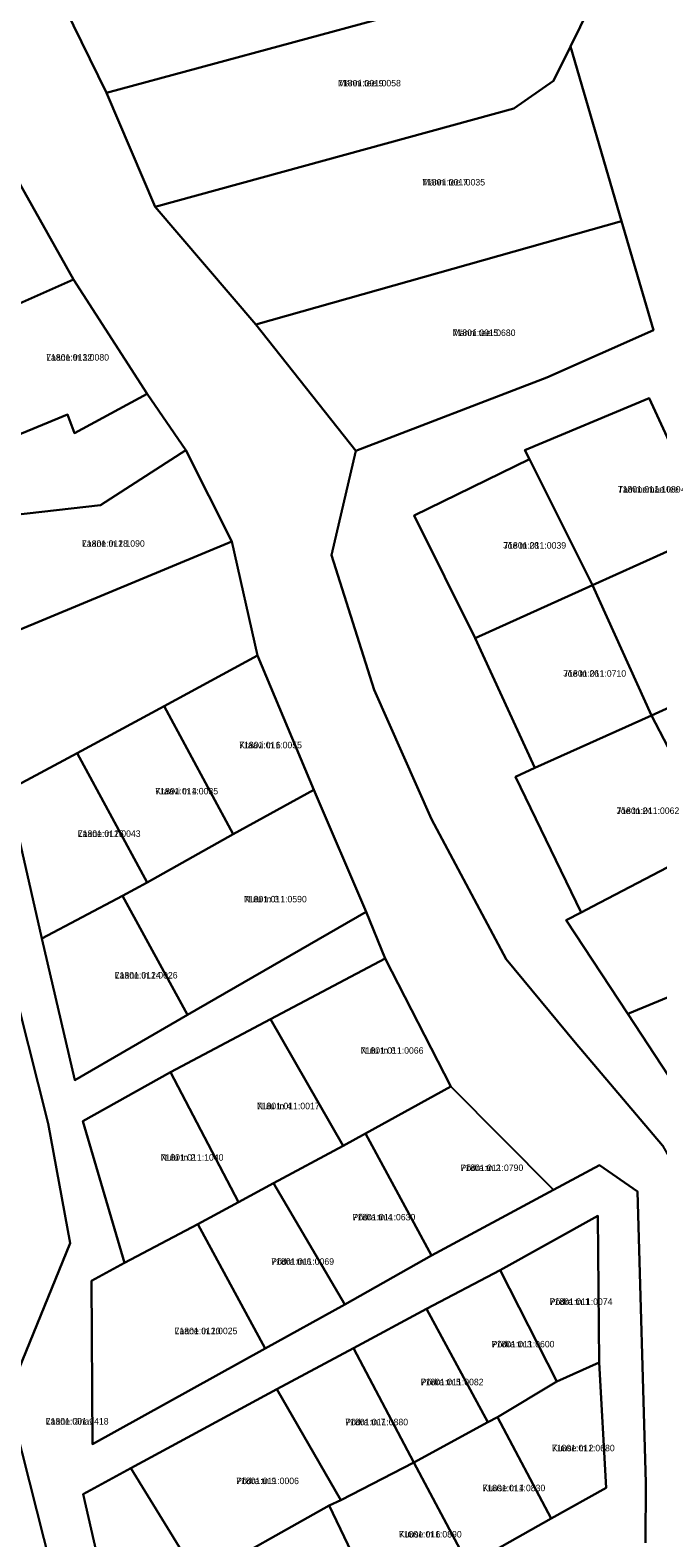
# Model space of a CAD drawing. Extents: x 529768 to 552006, y 6562269 to 6580975.
# Drawn here: x 537735.3 to 537880.2, y 6574791.4 to 6575139.4 of the extents above; entities that cross this region are included whole.
import ezdxf

# ---------------------------------------------------------------- set-up
doc = ezdxf.new("R2010")
doc.units = 0
for name, color, linetype in [('L_AADRESS', 7, 'Continuous'), ('PIIR', 7, 'Continuous'), ('TUNNUS', 7, 'Continuous')]:
    doc.layers.add(name, color=color, linetype=linetype)

msp = doc.modelspace()

# ---------------------------------------------------------------- linework, layer by layer
at = {"layer": 'PIIR'}
for points in [[(537861.04, 6575154.26), (537752.93, 6575124.92), (537739.57, 6575152.36), (537753.02, 6575156.04), (537846.64, 6575181.62)], [(537861.04, 6575154.26), (537864.51, 6575144.75), (537860.06, 6575135.67), (537856.14, 6575127.7), (537847, 6575121.36), (537764.17, 6575098.61), (537752.93, 6575124.92)], [(537847, 6575121.36), (537856.14, 6575127.7), (537860.06, 6575135.67), (537871.85, 6575095.34), (537787.43, 6575071.47), (537764.17, 6575098.61)], [(537715.01, 6575068.35), (537700.13, 6575101.13), (537691.05, 6575109.25), (537721.93, 6575123.45), (537745.3, 6575081.84), (537718.25, 6575069.88)], [(537879.22, 6575070.16), (537854.59, 6575059.21), (537810.54, 6575042.33), (537787.43, 6575071.47), (537871.85, 6575095.34)], [(537726.91, 6575046.15), (537721.22, 6575061.64), (537718.25, 6575069.88), (537745.3, 6575081.84), (537762.35, 6575055.48), (537745.6, 6575046.36), (537743.96, 6575050.67), (537728.83, 6575044.46)], [(537726.91, 6575046.15), (537728.83, 6575044.46), (537743.96, 6575050.67), (537745.6, 6575046.36), (537762.35, 6575055.48), (537771.25, 6575042.48), (537751.6, 6575029.77), (537713.53, 6575025.44), (537725.15, 6574997.87), (537716.85, 6574994.41), (537697.03, 6575023.57), (537693.76, 6575030.37), (537713.43, 6575058.2), (537721.22, 6575061.64)], [(537823.98, 6575027.38), (537838.08, 6574999.09), (537851.84, 6574969.13), (537847.37, 6574967.05), (537862.52, 6574935.76), (537859.04, 6574933.96), (537873.29, 6574912.33), (537887.42, 6574890.88), (537915.26, 6574902.32), (537943.04, 6574913.53), (537943.83, 6574915.98), (537932.32, 6574943.91), (537922.07, 6574966.37), (537915.04, 6574980.87), (537907.57, 6574994.3), (537894.96, 6575019.57), (537894.46, 6575019.54), (537892.46, 6575023.64), (537878.24, 6575054.44), (537849.52, 6575042.51), (537850.57, 6575040.41)], [(537849.52, 6575042.51), (537878.24, 6575054.44), (537892.46, 6575023.64), (537865.15, 6575011.33), (537850.57, 6575040.41)], [(537713.53, 6575025.44), (537751.6, 6575029.77), (537771.25, 6575042.48), (537781.86, 6575021.43), (537725.15, 6574997.87)], [(537850.57, 6575040.41), (537865.15, 6575011.33), (537838.08, 6574999.09), (537823.98, 6575027.38)], [(537865.15, 6575011.33), (537892.46, 6575023.64), (537894.46, 6575019.54), (537894.96, 6575019.57), (537907.57, 6574994.3), (537878.76, 6574981.24)], [(537838.08, 6574999.09), (537865.15, 6575011.33), (537878.76, 6574981.24), (537851.84, 6574969.13)], [(537782.23, 6574953.83), (537766.3, 6574983.41), (537787.82, 6574995.05), (537800.84, 6574964.08)], [(537878.76, 6574981.24), (537907.57, 6574994.3), (537915.04, 6574980.87), (537886.29, 6574966.76)], [(537746.19, 6574972.53), (537766.3, 6574983.41), (537782.23, 6574953.83), (537762.37, 6574942.71)], [(537878.76, 6574981.24), (537886.29, 6574966.76), (537892.86, 6574951.6), (537865.15, 6574937.12), (537862.52, 6574935.76), (537847.37, 6574967.05), (537851.84, 6574969.13)], [(537746.19, 6574972.53), (537762.37, 6574942.71), (537756.62, 6574939.57), (537738.05, 6574929.75), (537730.27, 6574963.99)], [(537812.88, 6574935.9), (537771.68, 6574912.1), (537756.62, 6574939.57), (537762.37, 6574942.71), (537782.23, 6574953.83), (537800.84, 6574964.08)], [(537575.1, 6574793.51), (537567.33, 6574887.8), (537721.06, 6574959.69), (537739.46, 6574887.08), (537744.59, 6574859.46), (537730.17, 6574824.12), (537691.03, 6574813.55), (537680.26, 6574772.23), (537701.22, 6574747.22), (537673.77, 6574708.6), (537642.67, 6574704.19), (537621.56, 6574706.93), (537618.19, 6574702.52), (537588.02, 6574714.43), (537548.93, 6574726.02), (537540.02, 6574788.31)], [(537859.04, 6574933.96), (537862.52, 6574935.76), (537865.15, 6574937.12), (537892.86, 6574951.6), (537902.36, 6574931.19), (537904.81, 6574925.39), (537873.29, 6574912.33)], [(537738.05, 6574929.75), (537756.62, 6574939.57), (537771.68, 6574912.1), (537745.63, 6574897.07)], [(537807.61, 6574881.89), (537790.79, 6574911.14), (537817.25, 6574925.17), (537832.47, 6574895.6), (537812.78, 6574884.74)], [(537873.29, 6574912.33), (537904.81, 6574925.39), (537915.26, 6574902.32), (537887.42, 6574890.88)], [(537790.79, 6574911.14), (537807.61, 6574881.89), (537791.48, 6574873.27), (537783.43, 6574868.9), (537767.7, 6574898.93)], [(537767.7, 6574898.93), (537783.43, 6574868.9), (537774.03, 6574863.8), (537757.12, 6574854.89), (537747.47, 6574887.56)], [(537828.01, 6574856.55), (537812.78, 6574884.74), (537832.47, 6574895.6), (537856.17, 6574871.76)], [(537807.94, 6574845.29), (537791.48, 6574873.27), (537807.61, 6574881.89), (537812.78, 6574884.74), (537828.01, 6574856.55)], [(537774.03, 6574863.8), (537783.43, 6574868.9), (537791.48, 6574873.27), (537807.94, 6574845.29), (537789.59, 6574835.11)], [(537747.59, 6574801.5), (537760.71, 6574743.92), (537787.55, 6574756.29), (537817.1, 6574772.66), (537816.46, 6574773.66), (537836.52, 6574785.11), (537855.61, 6574795.89), (537868.32, 6574802.94), (537866.69, 6574831.89), (537866.35, 6574865.77), (537843.83, 6574853.22), (537826.82, 6574844.29), (537809.98, 6574835.16), (537792.24, 6574825.71), (537758.6, 6574807.48)], [(537749.69, 6574813.04), (537749.48, 6574850.76), (537757.12, 6574854.89), (537774.03, 6574863.8), (537789.59, 6574835.11)], [(537843.83, 6574853.22), (537866.35, 6574865.77), (537866.69, 6574831.89), (537856.93, 6574827.5)], [(537856.93, 6574827.5), (537843.23, 6574819.29), (537841.02, 6574818.08), (537826.82, 6574844.29), (537843.83, 6574853.22)], [(537809.98, 6574835.16), (537826.82, 6574844.29), (537841.02, 6574818.08), (537823.9, 6574808.82)], [(537807.06, 6574800.11), (537792.24, 6574825.71), (537809.98, 6574835.16), (537823.9, 6574808.82)], [(537855.61, 6574795.89), (537843.23, 6574819.29), (537856.93, 6574827.5), (537866.69, 6574831.89), (537868.32, 6574802.94)], [(537792.24, 6574825.71), (537807.06, 6574800.11), (537804.38, 6574798.9), (537774.23, 6574781.91), (537758.6, 6574807.48)], [(537730.17, 6574824.12), (537740.19, 6574784.56), (537680.26, 6574772.23), (537691.03, 6574813.55)], [(537836.52, 6574785.11), (537823.9, 6574808.82), (537841.02, 6574818.08), (537843.23, 6574819.29), (537855.61, 6574795.89)], [(537760.71, 6574743.92), (537747.59, 6574801.5), (537758.6, 6574807.48), (537774.23, 6574781.91), (537787.55, 6574756.29)], [(537804.38, 6574798.9), (537807.06, 6574800.11), (537823.9, 6574808.82), (537836.52, 6574785.11), (537816.46, 6574773.66)], [(537804.38, 6574798.9), (537816.46, 6574773.66), (537817.1, 6574772.66), (537787.55, 6574756.29), (537774.23, 6574781.91)]]:
    msp.add_lwpolyline(points, close=True, dxfattribs=at)
for points in [[(537877.38, 6574790.27), (537877.44, 6574804.07), (537875.56, 6574871.37), (537866.76, 6574877.46), (537856.17, 6574871.76), (537832.47, 6574895.6), (537817.25, 6574925.17), (537812.88, 6574935.9), (537800.84, 6574964.08), (537787.82, 6574995.05), (537781.86, 6575021.43), (537771.25, 6575042.48), (537762.35, 6575055.48), (537745.3, 6575081.84), (537721.93, 6575123.45), (537716.1, 6575133.86), (537715.18, 6575135.41), (537718.33, 6575135.79), (537727.22, 6575136.84), (537718.28, 6575152.24)], [(537739.57, 6575152.36), (537752.93, 6575124.92), (537764.17, 6575098.61), (537787.43, 6575071.47), (537810.54, 6575042.33), (537804.89, 6575018.22), (537814.75, 6574987.16), (537827.97, 6574957.32), (537845.19, 6574925.01), (537861.18, 6574905.72), (537881.31, 6574881.94), (537891.99, 6574862.91), (537895.3, 6574837.6), (537906.26, 6574838.65), (537911.06, 6574804.7), (537903.95, 6574801.98), (537904.83, 6574769.93)], [(537881.31, 6574881.94), (537861.18, 6574905.72), (537845.19, 6574925.01), (537827.97, 6574957.32), (537814.75, 6574987.16), (537804.89, 6575018.22), (537810.54, 6575042.33), (537854.59, 6575059.21), (537879.22, 6575070.16), (537871.85, 6575095.34), (537860.06, 6575135.67), (537864.51, 6575144.75)], [(537725.15, 6574997.87), (537781.86, 6575021.43), (537787.82, 6574995.05), (537766.3, 6574983.41), (537746.19, 6574972.53), (537730.27, 6574963.99), (537738.05, 6574929.75), (537745.63, 6574897.07), (537771.68, 6574912.1), (537812.88, 6574935.9), (537817.25, 6574925.17), (537790.79, 6574911.14), (537767.7, 6574898.93), (537747.47, 6574887.56), (537757.12, 6574854.89), (537749.48, 6574850.76), (537749.69, 6574813.04), (537789.59, 6574835.11), (537807.94, 6574845.29), (537828.01, 6574856.55), (537856.17, 6574871.76), (537866.76, 6574877.46), (537875.56, 6574871.37), (537877.44, 6574804.07), (537877.38, 6574790.27)], [(537740.19, 6574784.56), (537730.17, 6574824.12), (537744.59, 6574859.46), (537739.46, 6574887.08), (537721.06, 6574959.69)]]:
    msp.add_lwpolyline(points, dxfattribs=at)

# ---------------------------------------------------------------- texts
at = {"layer": 'L_AADRESS'}
for s, p in [('Männi tee 9', (537806.41, 6575126.44)), ('Männi tee 7', (537825.84, 6575103.57)), ('Männi tee 5', (537832.88, 6575068.83)), ('Laane tn 32', (537739.03, 6575063.15)), ('Tammemäe tee 4', (537870.99, 6575032.7)), ('Laane tn 28', (537747.29, 6575020.18)), ('Jõe tn 28', (537844.56, 6575019.74)), ('Jõe tn 26', (537858.42, 6574990.19)), ('Kraavi tn 6', (537783.57, 6574973.66)), ('Kraavi tn 4', (537764.21, 6574963.01)), ('Jõe tn 24', (537870.69, 6574958.5)), ('Laane tn 26', (537746.32, 6574953.21)), ('Nulu tn 3', (537784.69, 6574938.09)), ('Laane tn 24', (537754.86, 6574920.52)), ('Nulu tn 6', (537811.63, 6574903.15)), ('Nulu tn 4', (537787.66, 6574890.34)), ('Nulu tn 2', (537765.45, 6574878.47)), ('Põdra tn 2', (537834.67, 6574876.08)), ('Põdra tn 4', (537809.74, 6574864.68)), ('Põdra tn 6', (537790.98, 6574854.44)), ('Põdra tn 1', (537855.26, 6574845.18)), ('Laane tn 20', (537768.67, 6574838.42)), ('Põdra tn 3', (537841.88, 6574835.37)), ('Põdra tn 5', (537825.5, 6574826.63)), ('Laane tänav', (537738.93, 6574817.56)), ('Põdra tn 7', (537808.07, 6574817.39)), ('Kuuse tn 2', (537855.77, 6574811.39)), ('Põdra tn 9', (537782.88, 6574803.81)), ('Kuuse tn 4', (537839.75, 6574802.17)), ('Kuuse tn 6', (537820.45, 6574791.49))]:
    msp.add_text(s, height=1.5, dxfattribs=at).set_placement(p)
at = {"layer": 'TUNNUS'}
for s, p in [('71801:001:0058', (537806.41, 6575126.44)), ('71801:001:0035', (537825.84, 6575103.57)), ('71801:001:0680', (537832.88, 6575068.83)), ('71801:011:0080', (537739.03, 6575063.15)), ('71801:011:1080', (537870.99, 6575032.7)), ('71801:011:1090', (537747.29, 6575020.18)), ('71801:011:0039', (537844.56, 6575019.74)), ('71801:011:0710', (537858.42, 6574990.19)), ('71801:011:0055', (537783.57, 6574973.66)), ('71801:011:0035', (537764.21, 6574963.01)), ('71801:011:0062', (537870.69, 6574958.5)), ('71801:011:0043', (537746.32, 6574953.21)), ('71801:011:0590', (537784.69, 6574938.09)), ('71801:011:0026', (537754.86, 6574920.52)), ('71801:011:0066', (537811.63, 6574903.15)), ('71801:011:0017', (537787.66, 6574890.34)), ('71801:011:1040', (537765.45, 6574878.47)), ('71801:011:0790', (537834.67, 6574876.08)), ('71801:011:0630', (537809.74, 6574864.68)), ('71801:011:0069', (537790.98, 6574854.44)), ('71801:011:0074', (537855.26, 6574845.18)), ('71801:011:0025', (537768.67, 6574838.42)), ('71801:011:0600', (537841.88, 6574835.37)), ('71801:011:0082', (537825.5, 6574826.63)), ('71801:001:1418', (537738.93, 6574817.56)), ('71801:011:0880', (537808.07, 6574817.39)), ('71801:011:0680', (537855.77, 6574811.39)), ('71801:011:0006', (537782.88, 6574803.81)), ('71801:011:0830', (537839.75, 6574802.17)), ('71801:011:0890', (537820.45, 6574791.49))]:
    msp.add_text(s, height=1.5, dxfattribs=at).set_placement(p)

doc.saveas('drawing.dxf')
